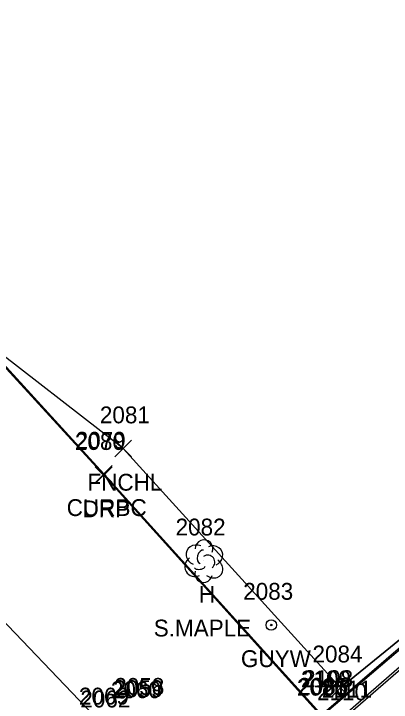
# Model space of a CAD drawing. Extents: x 1462668 to 1465147, y 550359 to 557351.
# Drawn here: x 1464725.3 to 1464770.2, y 552827.8 to 552909.6 of the extents above; entities that cross this region are included whole.
import ezdxf

# ---------------------------------------------------------------- set-up
doc = ezdxf.new("R2010")
doc.units = 0
for name, color, linetype in [('L_A', 7, 'Continuous'), ('L_C', 7, 'Continuous'), ('L_I', 7, 'Continuous'), ('L_TIC', 7, 'Continuous'), ('LELB', 7, 'Continuous'), ('Level 6', 7, 'Continuous'), ('LFNC', 7, 'Continuous'), ('LTD', 7, 'Continuous'), ('LW', 7, 'Continuous'), ('R_A', 7, 'Continuous'), ('R_I', 7, 'Continuous'), ('R_TIC', 7, 'Continuous'), ('RC', 7, 'Continuous'), ('RDP', 7, 'Continuous'), ('U_A', 7, 'Continuous'), ('U_I', 7, 'Continuous'), ('UPGW', 7, 'Continuous')]:
    doc.layers.add(name, color=color, linetype=linetype)

msp = doc.modelspace()

# ---------------------------------------------------------------- linework, layer by layer
at = {"layer": 'L_TIC'}
for points in [[(1464737.324, 552856.979), (1464739.324, 552858.979)], [(1464739.324, 552856.979), (1464737.324, 552858.979)], [(1464763.181, 552828.574), (1464765.181, 552830.574)], [(1464765.181, 552828.574), (1464763.181, 552830.574)]]:
    msp.add_lwpolyline(points, dxfattribs=at)
at = {"layer": 'LELB'}
msp.add_lwpolyline([(1464776.974, 552839.276), (1464762.247, 552826.603), (1464763.597, 552825.073), (1464778.499, 552837.995)], dxfattribs=at)
at = {"layer": 'Level 6'}
msp.add_lwpolyline([(1464838.403, 552909.627), (1464825.572, 552898.882), (1464814.887, 552890.132), (1464814.846, 552890.046), (1464812.513, 552887.593), (1464808.178, 552883.866), (1464807.229, 552883.511), (1464807.237, 552883.375), (1464816.51, 552872.931), (1464798.305, 552856.334), (1464792.194, 552850.687), (1464778.291, 552838.102), (1464776.974, 552839.546), (1464776.514, 552839.567), (1464764.181, 552829.574), (1464738.324, 552857.979), (1464721.109, 552871.274)], dxfattribs=at)
at = {"layer": 'LFNC'}
msp.add_lwpolyline([(1464738.324, 552857.979), (1464764.181, 552829.574), (1464776.514, 552839.567)], dxfattribs=at)
at = {"layer": 'LTD'}
msp.add_line((1464747.897, 552844.657), (1464747.897, 552844.657), dxfattribs=at)
msp.add_line((1464747.897, 552844.657), (1464747.897, 552844.657), dxfattribs=at)
msp.add_arc((1464747.944, 552846.091), 1.047, 335.52715, 180.95627, dxfattribs=at)
for centre, major_axis, ratio, start_param, end_param in [((1464747.106, 552845.324), (1.21, -0.512), 0.895232, 1.570796, 4.712389), ((1464748.939, 552845.241), (-1.141, -0.483), 0.949671, 1.570796, 4.712389), ((1464747.689, 552845.116), (-0.208, -0.792), 0.645439, 3.141593, 6.283185), ((1464746.814, 552843.949), (0.584, -1.042), 0.959034, 3.141593, 6.283185), ((1464748.397, 552844.491), (-0.5, 0.667), 0.989748, 3.141593, 6.283185), ((1464748.898, 552843.824), (-1.09, 0.792), 0.841452, 1.570796, 4.712389), ((1464747.898, 552843.157), (0.265, 1.061), 0.942809, 1.570796, 4.712389), ((1464747.439, 552843.907), (-0.625, -0.083), 0.423636, 0, 3.141593)]:
    msp.add_ellipse(centre, major_axis=major_axis, ratio=ratio, start_param=start_param, end_param=end_param, dxfattribs=at)
at = {"layer": 'LW'}
msp.add_lwpolyline([(1464777.207, 552839.18), (1464762.497, 552826.649), (1464763.526, 552825.402), (1464778.195, 552838.162)], dxfattribs=at)
at = {"layer": 'R_TIC'}
for points in [[(1464735.01, 552853.815), (1464737.01, 552855.815)], [(1464737.01, 552853.815), (1464735.01, 552855.815)], [(1464735.026, 552853.965), (1464737.026, 552855.965)], [(1464737.026, 552853.965), (1464735.026, 552855.965)]]:
    msp.add_lwpolyline(points, dxfattribs=at)
at = {"layer": 'RC'}
msp.add_lwpolyline([(1464696.246, 552898.455), (1464736.026, 552854.965), (1464762.479, 552825.738), (1464765.877, 552822.098), (1464766.303, 552822.527)], dxfattribs=at)
at = {"layer": 'RDP'}
for points in [[(1464696.032, 552898.409), (1464736.01, 552854.815), (1464762.385, 552825.632), (1464765.662, 552821.925), (1464765.829, 552821.71), (1464771.539, 552815.661), (1464775.816, 552813.338), (1464781.57, 552812.214)], [(1464704.321, 552858.135), (1464736.456, 552824.575)]]:
    msp.add_lwpolyline(points, dxfattribs=at)
at = {"layer": 'UPGW'}
for radius in [0.625, 0.0833]:
    msp.add_circle((1464755.939, 552837.02), radius, dxfattribs=at)

# ---------------------------------------------------------------- texts
at = {"layer": 'L_A'}
for s, p in [('FNCHL', (1464734.072, 552852.979)), ('H', (1464747.331, 552839.657))]:
    msp.add_text(s, height=2, dxfattribs=at).set_placement(p)
at = {"layer": 'L_C'}
msp.add_text('S.MAPLE', height=2, dxfattribs=at).set_placement((1464741.96, 552835.657))
at = {"layer": 'L_I'}
for s, p in [('2081', (1464735.552, 552860.979)), ('2082', (1464744.559, 552847.657)), ('2084', (1464760.842, 552832.574)), ('2109', (1464759.467, 552829.603)), ('2108', (1464759.725, 552829.649)), ('2060', (1464736.864, 552828.327)), ('2111', (1464761.967, 552828.402)), ('2110', (1464761.384, 552828.073)), ('2062', (1464733.232, 552827.23))]:
    msp.add_text(s, height=2, dxfattribs=at).set_placement(p)
at = {"layer": 'R_A'}
for s, p in [('CURBC', (1464731.609, 552849.965)), ('DRP', (1464733.498, 552849.815))]:
    msp.add_text(s, height=2, dxfattribs=at).set_placement(p)
at = {"layer": 'R_I'}
for s, p in [('2080', (1464732.585, 552857.815)), ('2079', (1464732.68, 552857.965)), ('2059', (1464737.158, 552828.453)), ('2058', (1464737.27, 552828.723)), ('2086', (1464758.991, 552828.632)), ('2085', (1464759.14, 552828.738)), ('2069', (1464733.062, 552827.575))]:
    msp.add_text(s, height=2, dxfattribs=at).set_placement(p)
at = {"layer": 'U_A'}
msp.add_text('GUYW', height=2, dxfattribs=at).set_placement((1464752.332, 552832.02))
at = {"layer": 'U_I'}
msp.add_text('2083', height=2, dxfattribs=at).set_placement((1464752.6, 552840.02))

doc.saveas('drawing.dxf')
